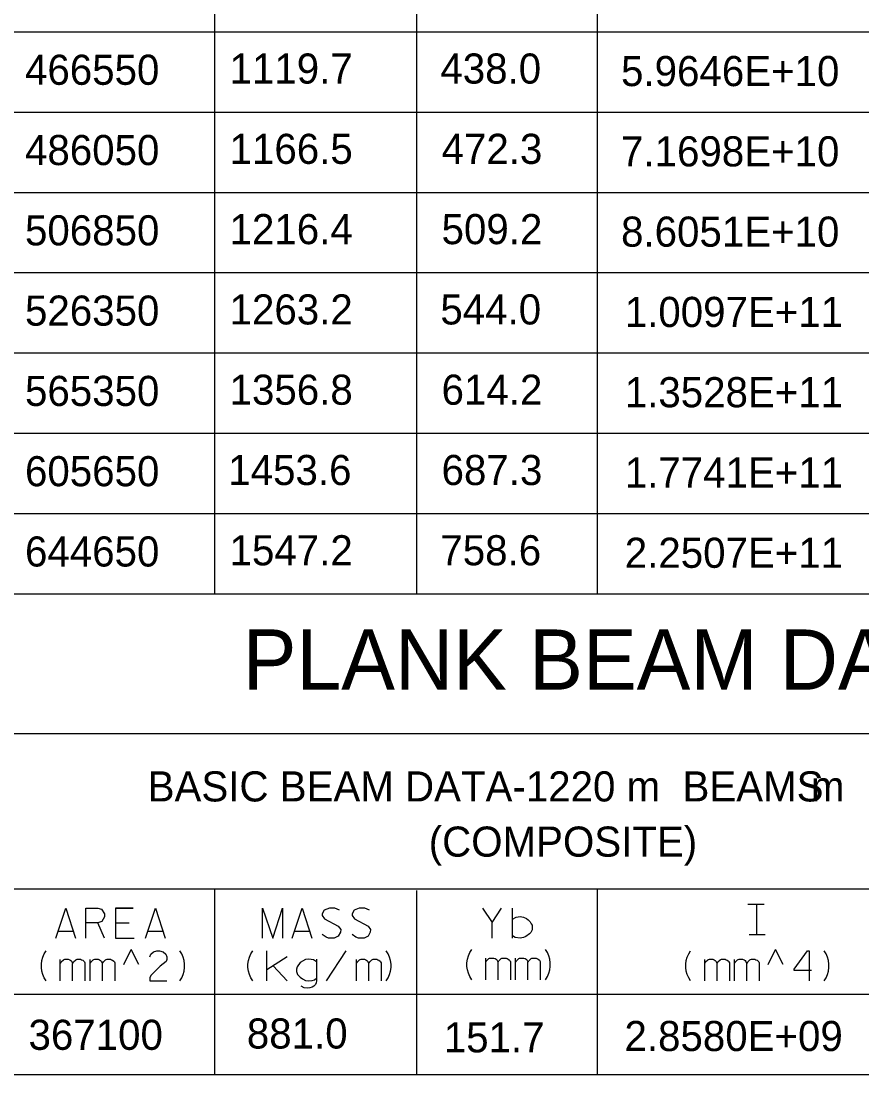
# Model space of a CAD drawing. Extents: x 635698 to 639877, y 296617 to 300175.
# Drawn here: x 636660.9 to 636744.7, y 299839.7 to 299944.7 of the extents above; entities that cross this region are included whole.
import ezdxf

# ---------------------------------------------------------------- set-up
doc = ezdxf.new("R2010")
doc.units = 0
doc.layers.add('2', color=7, linetype='Continuous')

msp = doc.modelspace()

# ---------------------------------------------------------------- linework, layer by layer
at = {"layer": '2'}
for p, q in [((636680.19, 300010.07), (636680.19, 299887.57)), ((636700.31, 300010.07), (636700.31, 299887.57)), ((636718.31, 300010.07), (636718.31, 299887.57)), ((636818.44, 299943.57), (636635.94, 299943.57)), ((636818.44, 299935.57), (636635.94, 299935.57)), ((636818.44, 299927.57), (636635.94, 299927.57)), ((636818.44, 299919.57), (636635.94, 299919.57)), ((636818.44, 299911.57), (636635.94, 299911.57)), ((636818.44, 299903.57), (636635.94, 299903.57)), ((636818.44, 299895.57), (636635.94, 299895.57)), ((637001.69, 299887.57), (636635.94, 299887.57)), ((637001.69, 299873.66), (636618.31, 299873.66)), ((636818.44, 299858.16), (636635.94, 299858.16)), ((636680.19, 299858.16), (636680.19, 299839.66)), ((636700.31, 299858.03), (636700.31, 299839.66)), ((636718.31, 299858.16), (636718.31, 299839.66)), ((636733.31, 299856.66), (636734.94, 299856.66)), ((636733.44, 299853.66), (636735.06, 299853.66)), ((636671.14, 299850.65), (636671.89, 299852.15)), ((636672.64, 299850.65), (636671.89, 299852.15)), ((636735.34, 299850.65), (636736.09, 299852.15)), ((636736.84, 299850.65), (636736.09, 299852.15)), ((636818.44, 299847.66), (636635.94, 299847.66)), ((637001.69, 299839.66), (636618.31, 299839.66))]:
    msp.add_line(p, q, dxfattribs=at)
for points in [[(636664.39, 299853.29), (636665.38, 299856.29), (636666.35, 299853.29)], [(636667.36, 299853.29), (636667.36, 299856.29), (636668.57, 299856.29), (636668.92, 299856.17), (636669.23, 299855.7), (636669.23, 299855.42), (636668.95, 299854.94), (636668.57, 299854.83), (636667.36, 299854.83)], [(636672.07, 299856.29), (636670.34, 299856.29), (636670.34, 299853.29), (636672.18, 299853.29)], [(636670.34, 299856.29), (636672.07, 299856.29)], [(636673.32, 299853.29), (636674.31, 299856.29), (636675.28, 299853.29)], [(636684.96, 299853.29), (636684.96, 299856.29), (636686, 299853.29), (636686.97, 299856.29), (636686.97, 299853.29)], [(636687.94, 299853.29), (636688.93, 299856.29), (636689.9, 299853.29)], [(636692.64, 299856.08), (636692.17, 299856.29), (636691.63, 299856.29), (636691.13, 299856.08), (636690.92, 299855.7), (636690.92, 299855.56), (636691.15, 299855.2), (636692.52, 299854.5), (636692.76, 299854.16), (636692.74, 299853.88), (636692.52, 299853.5), (636692.12, 299853.29), (636691.56, 299853.29), (636691.3, 299853.38), (636690.92, 299853.64)], [(636695.62, 299856.08), (636695.15, 299856.29), (636694.6, 299856.29), (636694.11, 299856.08), (636693.89, 299855.7), (636693.89, 299855.56), (636694.13, 299855.2), (636695.5, 299854.5), (636695.74, 299854.16), (636695.71, 299853.88), (636695.5, 299853.5), (636695.1, 299853.29), (636694.53, 299853.29), (636694.27, 299853.38), (636693.89, 299853.64)], [(636706.89, 299856.29), (636707.84, 299854.85), (636708.78, 299856.29)], [(636709.87, 299853.29), (636709.87, 299856.29)], [(636733.85, 299856.66), (636734.56, 299856.66)], [(636734.2, 299853.66), (636734.2, 299856.66)], [(636709.87, 299855.18), (636710.25, 299855.39), (636710.63, 299855.44), (636710.96, 299855.39), (636711.26, 299855.25), (636711.45, 299855.13), (636711.64, 299854.92), (636711.74, 299854.73), (636711.83, 299854.57), (636711.83, 299854.12), (636711.69, 299853.86), (636711.57, 299853.72), (636711.22, 299853.46), (636710.98, 299853.34), (636710.63, 299853.29), (636710.15, 299853.34), (636709.87, 299853.53)], [(636669.23, 299853.29), (636668.55, 299854.83)], [(636670.34, 299854.8), (636671.69, 299854.8)], [(636670.34, 299854.8), (636671.69, 299854.8)], [(636707.84, 299853.29), (636707.84, 299854.85)], [(636664.62, 299854), (636666.11, 299854)], [(636673.55, 299854), (636675.04, 299854)], [(636688.18, 299854), (636689.67, 299854)], [(636733.85, 299853.66), (636734.56, 299853.66)], [(636663.42, 299849.04), (636663.23, 299849.34), (636663.09, 299849.67), (636662.99, 299850), (636662.95, 299850.36), (636662.95, 299850.71), (636662.99, 299851.07), (636663.09, 299851.4), (636663.23, 299851.73), (636663.42, 299852.04)], [(636673.75, 299851.42), (636673.85, 299851.71), (636674.11, 299851.94), (636674.46, 299852.04), (636674.72, 299852.04), (636675.07, 299851.94), (636675.33, 299851.68), (636675.45, 299851.42), (636675.45, 299851.16), (636675.36, 299850.95), (636674.77, 299850.5), (636673.85, 299849.56), (636673.75, 299849.32), (636673.75, 299849.04), (636675.45, 299849.04)], [(636676.73, 299849.04), (636676.92, 299849.34), (636677.06, 299849.67), (636677.15, 299850), (636677.2, 299850.36), (636677.2, 299850.71), (636677.15, 299851.07), (636677.06, 299851.4), (636676.92, 299851.73), (636676.73, 299852.04)], [(636684, 299849.04), (636683.81, 299849.34), (636683.66, 299849.67), (636683.57, 299850), (636683.52, 299850.36), (636683.52, 299850.71), (636683.57, 299851.07), (636683.66, 299851.4), (636683.81, 299851.73), (636684, 299852.04)], [(636685.4, 299849.04), (636685.4, 299852.04)], [(636691.35, 299849.04), (636693.31, 299852.04)], [(636697.3, 299849.04), (636697.49, 299849.34), (636697.63, 299849.67), (636697.73, 299850), (636697.78, 299850.36), (636697.78, 299850.71), (636697.73, 299851.07), (636697.63, 299851.4), (636697.49, 299851.73), (636697.3, 299852.04)], [(636705.81, 299849.15), (636705.62, 299849.46), (636705.48, 299849.79), (636705.38, 299850.12), (636705.33, 299850.48), (636705.33, 299850.83), (636705.38, 299851.19), (636705.48, 299851.52), (636705.62, 299851.85), (636705.81, 299852.15)], [(636713.16, 299849.15), (636713.35, 299849.46), (636713.49, 299849.79), (636713.59, 299850.12), (636713.63, 299850.48), (636713.63, 299850.83), (636713.59, 299851.19), (636713.49, 299851.52), (636713.35, 299851.85), (636713.16, 299852.15)], [(636727.62, 299849.04), (636727.43, 299849.34), (636727.29, 299849.67), (636727.19, 299850), (636727.14, 299850.36), (636727.14, 299850.71), (636727.19, 299851.07), (636727.29, 299851.4), (636727.43, 299851.73), (636727.62, 299852.04)], [(636739.65, 299850.08), (636737.95, 299850.08), (636737.95, 299850.19), (636739.27, 299852.04), (636739.44, 299852.04), (636739.44, 299849.04)], [(636740.93, 299849.04), (636741.12, 299849.34), (636741.26, 299849.67), (636741.35, 299850), (636741.4, 299850.36), (636741.4, 299850.71), (636741.35, 299851.07), (636741.26, 299851.4), (636741.12, 299851.73), (636740.93, 299852.04)], [(636664.82, 299850.78), (636664.87, 299850.83), (636664.92, 299850.93), (636665.13, 299851.14), (636665.2, 299851.16), (636665.29, 299851.19), (636665.62, 299851.19), (636665.77, 299851.14), (636665.86, 299851.07), (636665.96, 299850.97), (636666.03, 299850.81), (636666.05, 299850.76), (636666.1, 299850.83), (636666.14, 299850.93), (636666.36, 299851.14), (636666.43, 299851.16), (636666.5, 299851.19), (636666.85, 299851.19), (636666.95, 299851.14), (636667.07, 299851.09), (636667.18, 299851), (636667.23, 299850.93), (636667.28, 299850.83), (636667.28, 299849.04)], [(636664.82, 299849.04), (636664.82, 299851.16)], [(636667.8, 299850.78), (636667.85, 299850.83), (636667.89, 299850.93), (636668.11, 299851.14), (636668.18, 299851.16), (636668.27, 299851.19), (636668.6, 299851.19), (636668.74, 299851.14), (636668.84, 299851.07), (636668.93, 299850.97), (636669, 299850.81), (636669.03, 299850.76), (636669.07, 299850.83), (636669.12, 299850.93), (636669.33, 299851.14), (636669.4, 299851.16), (636669.48, 299851.19), (636669.83, 299851.19), (636669.92, 299851.14), (636670.04, 299851.09), (636670.16, 299851), (636670.21, 299850.93), (636670.25, 299850.83), (636670.25, 299849.04)], [(636667.8, 299849.04), (636667.8, 299851.16)], [(636687.43, 299851.42), (636685.4, 299850.12)], [(636690.36, 299850.93), (636690.05, 299851.14), (636689.6, 299851.19), (636689.27, 299851.16), (636688.71, 299850.86), (636688.42, 299850.43), (636688.37, 299850.19), (636688.37, 299849.96), (636688.47, 299849.67), (636688.73, 299849.39), (636688.94, 299849.23), (636689.25, 299849.08), (636689.53, 299849.04), (636689.91, 299849.06), (636690.15, 299849.13), (636690.36, 299849.3)], [(636690.36, 299851.19), (636690.36, 299849.04), (636690.31, 299848.85), (636690.24, 299848.68), (636690.1, 299848.52), (636689.91, 299848.42), (636689.7, 299848.35), (636689.44, 299848.3), (636689.13, 299848.35), (636688.82, 299848.52)], [(636694.33, 299850.78), (636694.37, 299850.83), (636694.42, 299850.93), (636694.63, 299851.14), (636694.71, 299851.16), (636694.8, 299851.19), (636695.13, 299851.19), (636695.27, 299851.14), (636695.37, 299851.07), (636695.46, 299850.97), (636695.53, 299850.81), (636695.56, 299850.76), (636695.6, 299850.83), (636695.65, 299850.93), (636695.86, 299851.14), (636695.93, 299851.16), (636696, 299851.19), (636696.36, 299851.19), (636696.45, 299851.14), (636696.57, 299851.09), (636696.69, 299851), (636696.74, 299850.93), (636696.78, 299850.83), (636696.78, 299849.04)], [(636694.33, 299849.04), (636694.33, 299851.16)], [(636707.21, 299850.9), (636707.26, 299850.95), (636707.3, 299851.04), (636707.52, 299851.26), (636707.59, 299851.28), (636707.68, 299851.3), (636708.01, 299851.3), (636708.15, 299851.26), (636708.25, 299851.19), (636708.34, 299851.09), (636708.41, 299850.93), (636708.44, 299850.88), (636708.48, 299850.95), (636708.53, 299851.04), (636708.74, 299851.26), (636708.82, 299851.28), (636708.89, 299851.3), (636709.24, 299851.3), (636709.34, 299851.26), (636709.45, 299851.21), (636709.57, 299851.11), (636709.62, 299851.04), (636709.67, 299850.95), (636709.67, 299849.15)], [(636707.21, 299849.15), (636707.21, 299851.28)], [(636710.19, 299850.9), (636710.23, 299850.95), (636710.28, 299851.04), (636710.49, 299851.26), (636710.56, 299851.28), (636710.66, 299851.3), (636710.99, 299851.3), (636711.13, 299851.26), (636711.23, 299851.19), (636711.32, 299851.09), (636711.39, 299850.93), (636711.41, 299850.88), (636711.46, 299850.95), (636711.51, 299851.04), (636711.72, 299851.26), (636711.79, 299851.28), (636711.86, 299851.3), (636712.22, 299851.3), (636712.31, 299851.26), (636712.43, 299851.21), (636712.55, 299851.11), (636712.59, 299851.04), (636712.64, 299850.95), (636712.64, 299849.15)], [(636710.19, 299849.15), (636710.19, 299851.28)], [(636729.02, 299850.78), (636729.07, 299850.83), (636729.11, 299850.93), (636729.33, 299851.14), (636729.4, 299851.16), (636729.49, 299851.19), (636729.82, 299851.19), (636729.96, 299851.14), (636730.06, 299851.07), (636730.15, 299850.97), (636730.22, 299850.81), (636730.25, 299850.76), (636730.3, 299850.83), (636730.34, 299850.93), (636730.56, 299851.14), (636730.63, 299851.16), (636730.7, 299851.19), (636731.05, 299851.19), (636731.15, 299851.14), (636731.26, 299851.09), (636731.38, 299851), (636731.43, 299850.93), (636731.48, 299850.83), (636731.48, 299849.04)], [(636729.02, 299849.04), (636729.02, 299851.16)], [(636732, 299850.78), (636732.04, 299850.83), (636732.09, 299850.93), (636732.3, 299851.14), (636732.37, 299851.16), (636732.47, 299851.19), (636732.8, 299851.19), (636732.94, 299851.14), (636733.04, 299851.07), (636733.13, 299850.97), (636733.2, 299850.81), (636733.22, 299850.76), (636733.27, 299850.83), (636733.32, 299850.93), (636733.53, 299851.14), (636733.6, 299851.16), (636733.67, 299851.19), (636734.03, 299851.19), (636734.12, 299851.14), (636734.24, 299851.09), (636734.36, 299851), (636734.41, 299850.93), (636734.45, 299850.83), (636734.45, 299849.04)], [(636732, 299849.04), (636732, 299851.16)], [(636666.05, 299849.04), (636666.05, 299850.78)], [(636669.03, 299849.04), (636669.03, 299850.78)], [(636686.04, 299850.52), (636687.43, 299849.04)], [(636695.56, 299849.04), (636695.56, 299850.78)], [(636708.44, 299849.15), (636708.44, 299850.9)], [(636711.41, 299849.15), (636711.41, 299850.9)], [(636730.25, 299849.04), (636730.25, 299850.78)], [(636733.22, 299849.04), (636733.22, 299850.78)]]:
    msp.add_lwpolyline(points, dxfattribs=at)

# ---------------------------------------------------------------- texts
for s, height, p in [('466550', 3, (636661.31, 299938.32)), ('1119.7', 3, (636681.69, 299938.44)), ('438.0', 3, (636702.69, 299938.44)), ('5.9646E+10', 3, (636720.69, 299938.19)), ('486050', 3, (636661.31, 299930.32)), ('1166.5', 3, (636681.69, 299930.44)), ('472.3', 3, (636702.81, 299930.44)), ('7.1698E+10', 3, (636720.69, 299930.19)), ('506850', 3, (636661.31, 299922.32)), ('1216.4', 3, (636681.69, 299922.44)), ('509.2', 3, (636702.81, 299922.44)), ('8.6051E+10', 3, (636720.69, 299922.19)), ('526350', 3, (636661.31, 299914.32)), ('1263.2', 3, (636681.69, 299914.44)), ('544.0', 3, (636702.69, 299914.44)), ('1.0097E+11', 3, (636721.06, 299914.19)), ('565350', 3, (636661.31, 299906.32)), ('1356.8', 3, (636681.69, 299906.44)), ('614.2', 3, (636702.81, 299906.44)), ('1.3528E+11', 3, (636721.06, 299906.19)), ('1453.6', 3, (636681.56, 299898.44)), ('687.3', 3, (636702.81, 299898.44)), ('605650', 3, (636661.31, 299898.32)), ('1.7741E+11', 3, (636721.06, 299898.19)), ('644650', 3, (636661.31, 299890.32)), ('1547.2', 3, (636681.69, 299890.44)), ('758.6', 3, (636702.69, 299890.44)), ('2.2507E+11', 3, (636721.06, 299890.19)), ('PLANK BEAM DATA (COMPOSITE CONSTRUCTION)', 6, (636683, 299878.05)), ('BASIC BEAM DATA-1220 m  BEAMS', 3, (636673.53, 299866.91)), ('m', 3, (636739.6, 299866.91)), ('(COMPOSITE)', 3, (636701.53, 299861.41)), ('367100', 3, (636661.66, 299842.16)), ('881.0', 3, (636683.41, 299842.29)), ('151.7', 3, (636703.03, 299841.91)), ('2.8580E+09', 3, (636721.03, 299842.04))]:
    msp.add_text(s, height=height, dxfattribs=at).set_placement(p)

doc.saveas('drawing.dxf')
